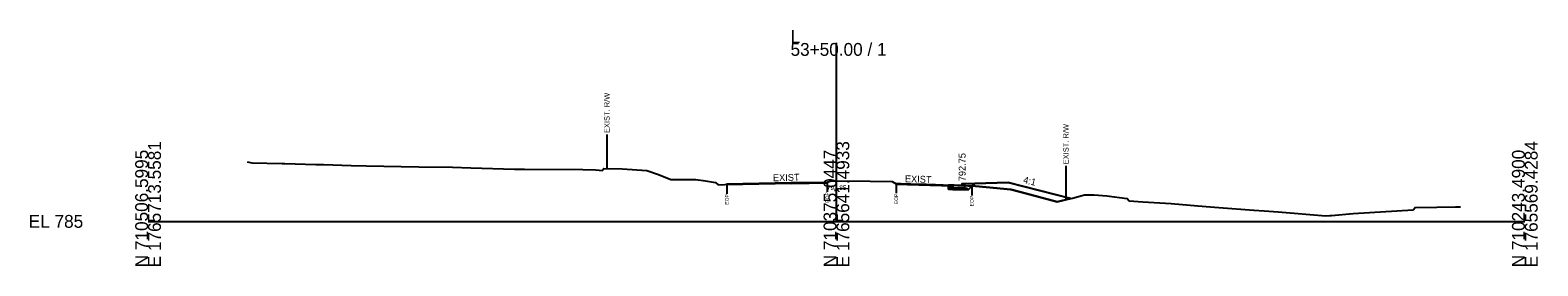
# Model space of a CAD drawing. Extents: x -26 to 5303, y -10 to 9578.
# Drawn here: x 3974.3 to 4302.8, y 3490.3 to 3541.7 of the extents above; entities that cross this region are included whole.
import ezdxf

# ---------------------------------------------------------------- set-up
doc = ezdxf.new("R2010")
doc.units = 0
for name, color, linetype in [('Exist Cross Section Cell', 7, 'Continuous'), ('Exist XS Ground Line', 7, 'Continuous'), ('Old_Level_10', 7, 'Continuous'), ('Old_Level_3', 7, 'Continuous'), ('Prop CMT Conc Surface', 7, 'Continuous'), ('Prop CMT Concrete Structures', 7, 'Continuous'), ('Prop CMT Pvmt Course 1', 7, 'Continuous'), ('Prop CMT Pvmt Course 1 CG', 7, 'Continuous'), ('Prop CMT Pvmt Course 2', 7, 'Continuous'), ('Prop CMT Pvmt Course 3', 7, 'Continuous'), ('Prop CMT Pvmt Surface', 7, 'Continuous'), ('Prop CMT Slope Grass', 7, 'Continuous'), ('Prop CMT Subgrade Earthwork', 7, 'Continuous'), ('Prop XS Earthwork Shape', 7, 'Continuous'), ('Prop XS Hydro Elevations', 7, 'Continuous'), ('Prop XS SE Text', 7, 'Continuous'), ('Prop XS Side Slope Text', 7, 'Continuous')]:
    doc.layers.add(name, color=color, linetype=linetype)

msp = doc.modelspace()

# ---------------------------------------------------------------- linework, layer by layer
at = {"layer": 'Exist Cross Section Cell'}
for p, q in [((4150, 3500), (4150, 3538.88)), ((4000, 3500), (4150, 3500)), ((4150, 3500), (4300, 3500))]:
    msp.add_line(p, q, dxfattribs=at)
at = {"layer": 'Exist XS Ground Line'}
msp.add_lwpolyline([(4021.62, 3512.96), (4021.93, 3512.91), (4022.58, 3512.77), (4029.24, 3512.6), (4029.82, 3512.59), (4036.56, 3512.41), (4038.2, 3512.37), (4044.25, 3512.18), (4047.56, 3512.11), (4059.02, 3511.86), (4066.35, 3511.79), (4070.36, 3511.68), (4079.84, 3511.39), (4082.06, 3511.36), (4094.73, 3511.34), (4097.47, 3511.22), (4098.31, 3511.16), (4098.93, 3511.06), (4099.34, 3511.55), (4103.32, 3511.48), (4108.7, 3511.08), (4111.25, 3510.19), (4113.89, 3509.15), (4116.78, 3509.15), (4119.39, 3509.15), (4121.46, 3508.8), (4123.63, 3508.44), (4124.21, 3507.98), (4125.66, 3508.05), (4126.15, 3508.08), (4126.53, 3508.09), (4127.19, 3508.1), (4128.67, 3508.13), (4129.69, 3508.15), (4131.52, 3508.19), (4132.72, 3508.23), (4134.56, 3508.26), (4134.9, 3508.27), (4136.4, 3508.3), (4137.22, 3508.33), (4137.84, 3508.33), (4138.71, 3508.35), (4139.35, 3508.35), (4140.1, 3508.37), (4141.92, 3508.4), (4142.92, 3508.41), (4143.77, 3508.43), (4145.3, 3508.45), (4145.78, 3508.46), (4146.79, 3508.47), (4147.44, 3508.5), (4148.01, 3508.51), (4148.39, 3508.66), (4148.9, 3508.87), (4150, 3508.85), (4157.34, 3508.73), (4162.14, 3508.68), (4163, 3508.2), (4163.57, 3508.18), (4164.02, 3508.17), (4165.73, 3508.1), (4166.12, 3508.08), (4168.58, 3508.02), (4171.43, 3507.99), (4173.23, 3507.95), (4174.28, 3507.92), (4174.98, 3507.89), (4175.67, 3507.87), (4176.37, 3507.85), (4177.13, 3507.81), (4178.65, 3507.74), (4179.51, 3507.72), (4182.66, 3507.44), (4188, 3506.96), (4189.93, 3506.47), (4198.1, 3504.26), (4201.45, 3505.09), (4204.07, 3505.77), (4206.19, 3505.79), (4208.91, 3505.59), (4213.34, 3504.99), (4213.76, 3504.5), (4216.73, 3504.23), (4222.94, 3503.9), (4228.78, 3503.39), (4233.34, 3503.05), (4240.98, 3502.45), (4243.17, 3502.32), (4246.29, 3502.1), (4256.66, 3501.24), (4257.52, 3501.29), (4257.91, 3501.29), (4262.6, 3501.72), (4275.7, 3502.53), (4276.12, 3503.03), (4280.83, 3503.12), (4284.87, 3503.14), (4286.02, 3503.15)], dxfattribs=at)
at = {"layer": 'Old_Level_10'}
for p, q in [((4099.98, 3518.94), (4099.98, 3511.54)), ((4200, 3512.13), (4200, 3504.73)), ((4126.15, 3508.08), (4126.15, 3506.03)), ((4148.01, 3508.51), (4148.01, 3506.46)), ((4163, 3508.2), (4163, 3506.15)), ((4179.51, 3507.72), (4179.51, 3505.67))]:
    msp.add_line(p, q, dxfattribs=at)
at = {"layer": 'Prop CMT Conc Surface'}
for points in [[(4175.39, 3507.89), (4177.39, 3507.75)], [(4177.39, 3507.75), (4177.39, 3508.25), (4177.89, 3508.25)]]:
    msp.add_lwpolyline(points, dxfattribs=at)
at = {"layer": 'Prop CMT Concrete Structures'}
for points in [[(4175.39, 3507.89), (4177.39, 3507.75), (4177.39, 3508.25), (4177.89, 3508.25)], [(4177.89, 3508.25), (4177.89, 3507.23), (4175.39, 3507.3)], [(4175.39, 3507.3), (4175.39, 3507.89)]]:
    msp.add_lwpolyline(points, dxfattribs=at)
at = {"layer": 'Prop CMT Pvmt Course 1'}
for p, q in [((4140.1, 3508.25), (4126.15, 3507.95)), ((4140.1, 3508.25), (4148.01, 3508.38)), ((4163, 3508.08), (4175.39, 3507.76))]:
    msp.add_line(p, q, dxfattribs=at)
at = {"layer": 'Prop CMT Pvmt Course 1 CG'}
for points in [[(4175.39, 3507.3), (4178.39, 3507.21), (4178.73, 3506.87)], [(4175.39, 3506.97), (4175.39, 3507.3)], [(4178.73, 3506.87), (4175.39, 3506.97)]]:
    msp.add_lwpolyline(points, dxfattribs=at)
at = {"layer": 'Prop CMT Pvmt Course 2'}
for points in [[(4174.39, 3507.33), (4174.39, 3507.67)], [(4174.39, 3507.67), (4175.39, 3507.64)], [(4175.39, 3507.3), (4174.39, 3507.33)], [(4175.39, 3507.64), (4175.39, 3507.3)]]:
    msp.add_lwpolyline(points, dxfattribs=at)
at = {"layer": 'Prop CMT Pvmt Course 3'}
for points in [[(4174.39, 3507.33), (4175.39, 3507.3)], [(4174.39, 3507), (4174.39, 3507.33)], [(4175.39, 3506.97), (4174.39, 3507)], [(4175.39, 3507.3), (4175.39, 3506.97)]]:
    msp.add_lwpolyline(points, dxfattribs=at)
at = {"layer": 'Prop CMT Pvmt Surface'}
for p, q in [((4140.1, 3508.37), (4126.15, 3508.08)), ((4140.1, 3508.37), (4148.01, 3508.51)), ((4163, 3508.2), (4175.39, 3507.89)), ((4174.39, 3507.91), (4175.39, 3507.89))]:
    msp.add_line(p, q, dxfattribs=at)
at = {"layer": 'Prop CMT Slope Grass'}
msp.add_lwpolyline([(4177.89, 3508.25), (4187.39, 3508.44), (4201.1, 3505.01)], dxfattribs=at)
at = {"layer": 'Prop CMT Subgrade Earthwork'}
msp.add_line((4174.39, 3507), (4174.39, 3507.91), dxfattribs=at)
for points in [[(4174.39, 3507), (4175.39, 3506.97)], [(4175.39, 3506.97), (4178.73, 3506.87), (4180.16, 3508.29)]]:
    msp.add_lwpolyline(points, dxfattribs=at)
at = {"layer": 'Prop XS Earthwork Shape'}
for points in [[(4126.53, 3508.09), (4127.19, 3508.1), (4126.15, 3508.08)], [(4131.52, 3508.19), (4132.28, 3508.21), (4128.67, 3508.13), (4129.69, 3508.15)], [(4128.67, 3508.13), (4129.69, 3508.15), (4131.52, 3508.19), (4132.28, 3508.21)], [(4137.22, 3508.33), (4137.84, 3508.33), (4138.71, 3508.35), (4139.02, 3508.35), (4132.28, 3508.21), (4133.74, 3508.24), (4134.37, 3508.26), (4134.9, 3508.27)], [(4134.37, 3508.26), (4134.9, 3508.27), (4137.22, 3508.33), (4137.84, 3508.33), (4138.71, 3508.35), (4139.02, 3508.35), (4132.28, 3508.21), (4133.74, 3508.24)], [(4139.35, 3508.35), (4140.1, 3508.37), (4139.02, 3508.35)], [(4140.1, 3508.37), (4142.92, 3508.41), (4145.3, 3508.45), (4145.78, 3508.46), (4146.79, 3508.47), (4147.28, 3508.49)], [(4147.28, 3508.49), (4147.44, 3508.5), (4148.01, 3508.51)], [(4147.44, 3508.5), (4148.01, 3508.51), (4147.28, 3508.49)], [(4168.58, 3508.02), (4169.55, 3508.02), (4171.56, 3507.99), (4163, 3508.2), (4163.57, 3508.18), (4164.02, 3508.17), (4166.12, 3508.08), (4167.71, 3508.02)], [(4163, 3508.2), (4171.56, 3507.99), (4169.55, 3508.02), (4168.58, 3508.02), (4167.71, 3508.02), (4166.12, 3508.08), (4164.02, 3508.17), (4163.57, 3508.18)], [(4178.73, 3506.87), (4179.58, 3507.71), (4179.51, 3507.72), (4178.65, 3507.74), (4177.39, 3507.8), (4177.39, 3507.75), (4175.47, 3507.88), (4174.98, 3507.89), (4174.39, 3507.91), (4174.39, 3507), (4175.39, 3506.97)], [(4174.39, 3507), (4175.39, 3506.97), (4178.73, 3506.87), (4179.58, 3507.71), (4179.51, 3507.72), (4178.65, 3507.74), (4177.39, 3507.8), (4177.39, 3507.75), (4175.47, 3507.88), (4174.98, 3507.89), (4174.39, 3507.91)], [(4177.39, 3507.75), (4177.39, 3507.8), (4177.13, 3507.81), (4176.37, 3507.85), (4175.67, 3507.87), (4175.47, 3507.88)], [(4175.47, 3507.88), (4177.39, 3507.75), (4177.39, 3507.8), (4177.13, 3507.81), (4176.37, 3507.85), (4175.67, 3507.87)], [(4188, 3506.96), (4189.93, 3506.47), (4198.1, 3504.26), (4201.1, 3505.01), (4187.39, 3508.44), (4180.16, 3508.29), (4179.58, 3507.71), (4182.66, 3507.44)], [(4180.16, 3508.29), (4187.39, 3508.44), (4201.1, 3505.01), (4198.1, 3504.26), (4189.93, 3506.47), (4188, 3506.96), (4182.66, 3507.44), (4179.58, 3507.71)]]:
    msp.add_lwpolyline(points, close=True, dxfattribs=at)

# ---------------------------------------------------------------- texts
at = {"layer": 'Exist Cross Section Cell'}
for s, p in [('L', (4140, 3538.88)), ('53+50.00 / 1', (4140, 3536.08)), ('EL 785', (3974, 3498.6))]:
    msp.add_text(s, height=2.8, dxfattribs=at).set_placement(p)
for s, p in [('N 710506.5995', (4000, 3490)), ('E 1765713.5581', (4002.8, 3490)), ('N 710375.0447', (4150, 3490)), ('E 1765641.4933', (4152.8, 3490)), ('N 710243.4900', (4300, 3490)), ('E 1765569.4284', (4302.8, 3490))]:
    msp.add_text(s, height=2.8, rotation=90, dxfattribs=at).set_placement(p)
at = {"layer": 'Old_Level_10'}
for s, height, p in [('EXIST. R/W', 1.181, (4100.57, 3519.25)), ('EXIST. R/W', 1.181, (4200.59, 3512.44)), ('EOP', 0.787, (4126.54, 3503.63)), ('EOP', 0.787, (4148.4, 3504.06)), ('EOP', 0.787, (4163.4, 3503.76)), ('EOP', 0.787, (4179.9, 3503.27))]:
    msp.add_text(s, height=height, rotation=90, dxfattribs=at).set_placement(p)
at = {"layer": 'Old_Level_3'}
msp.add_text('793.85', height=1, dxfattribs=at).set_placement((4147.95, 3506.85))
at = {"layer": 'Prop XS Hydro Elevations'}
msp.add_text('792.75', height=1.5, rotation=90, dxfattribs=at).set_placement((4178.14, 3508.75))
at = {"layer": 'Prop XS SE Text'}
for rotation, p in [(1.5504, (4136.18, 3508.73)), (358.2816, (4164.9, 3508.54))]:
    msp.add_text('EXIST', height=1.5, rotation=rotation, dxfattribs=at).set_placement(p)
at = {"layer": 'Prop XS Side Slope Text'}
msp.add_text('4:1', height=1.5, rotation=345.9638, dxfattribs=at).set_placement((4190.58, 3508.41))

doc.saveas('drawing.dxf')
